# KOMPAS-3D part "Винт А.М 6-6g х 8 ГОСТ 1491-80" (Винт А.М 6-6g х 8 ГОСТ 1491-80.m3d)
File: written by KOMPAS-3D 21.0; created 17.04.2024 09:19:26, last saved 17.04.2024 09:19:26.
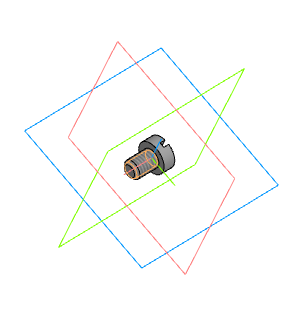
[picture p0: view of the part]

Document properties: Автор: Admin; Полное имя файла: C:\Users\wsr\Desktop\Чертежи\Винт А.М 6-6g х 8 ГОСТ 1491-80.m3d

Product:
- Part/product: Винт А.М 6-6g х 8 ГОСТ 1491-80
    Масса: 0.003569
  - Component [standard]: Винт А.М6-6gx8 ГОСТ 1491-80  | Масса: 0.003569; Раздел спецификации: Стандартные изделия; Рассекать на разрезах: no; source file: ..\..\..\..\Program Files\ASCON\KOMPAS-3D v21 Study\Libs\PARTLib\DATA\vault\methods\kompas\3d\PLib_Screw_GOST_1491_1500.m3d

Referenced files in C:\Program Files\ASCON\KOMPAS-3D v21 Study\Libs\PARTLib\DATA\vault\Methods\Kompas\3D\: PLib_Screw_GOST_1491_1500.m3d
